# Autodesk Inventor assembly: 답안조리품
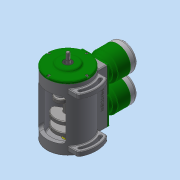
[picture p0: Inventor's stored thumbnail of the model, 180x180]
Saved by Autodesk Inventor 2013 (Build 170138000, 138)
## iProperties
Created: 2017-08
Part Number: 답안조리품
Document SubType Name: Assembly
Designer: dgall
Mass: 7431.31 g
Surface Area: 5102.67 cm^2
Volume: 2063.36 cm^3
Density: 3.60155 g/cm^3
Author: dgall
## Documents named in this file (16)
- C:\Users\dgall\Desktop\370807V1004\답안조리품.iam
- C:\Users\dgall\Desktop\370807V1004\본체.ipt
- C:\Users\dgall\Desktop\370807V1004\실린더.ipt
- C:\Users\dgall\Desktop\370807V1004\실린더헤드.ipt
- C:\Users\dgall\Desktop\370807V1004\볼트 M5 x 20.ipt
- C:\Users\dgall\Desktop\370807V1004\앞커버.ipt
- C:\Users\dgall\Desktop\370807V1004\베어링 12 x 28 x 8.ipt
- C:\Users\dgall\Desktop\370807V1004\오일 실 12 25 7.ipt
- C:\Users\dgall\Desktop\370807V1004\볼트 M4 x 8.ipt
- C:\Users\dgall\Desktop\370807V1004\크랭크축.ipt
- C:\Users\dgall\Desktop\370807V1004\커넥팅로드 엔드.ipt
- C:\Users\dgall\Desktop\370807V1004\커넥팅로드.ipt
- C:\Users\dgall\Desktop\370807V1004\피스톤.ipt
- C:\Users\dgall\Desktop\370807V1004\피스톤핀.ipt
- C:\Users\dgall\Desktop\370807V1004\너트 M4.ipt
- C:\Users\dgall\Desktop\370807V1004\육각 머리 볼트 M4 x 16.ipt
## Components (4 placed, 2 different names)
1. 피스톤:1
2. 피스톤핀:1
3. 피스톤:2
4. 피스톤핀:2
